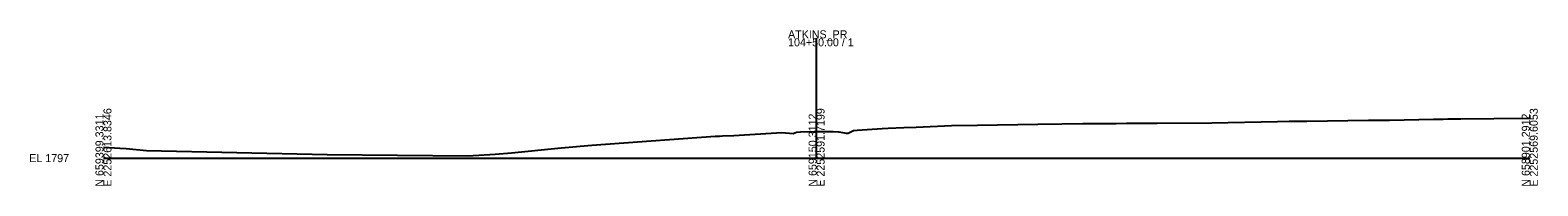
# Model space of a CAD drawing. Extents: x -11787 to 2342864, y -4773 to 646619.
# Drawn here: x 4530 to 5059, y 4059 to 4113 of the extents above; entities that cross this region are included whole.
import ezdxf

# ---------------------------------------------------------------- set-up
doc = ezdxf.new("R2010")
doc.units = 0
doc.layers.add('DESIGN - SHEET - Light Grid', color=7, linetype='Continuous')
doc.layers.add('SURVEY - GROUND - Top of Ground', color=7, linetype='Continuous')

msp = doc.modelspace()

# ---------------------------------------------------------------- linework, layer by layer
at = {"layer": 'DESIGN - SHEET - Light Grid'}
for p, q in [((4806.14, 4068.5), (4806.14, 4110.46)), ((4556.14, 4068.5), (4806.14, 4068.5)), ((4806.14, 4068.5), (5056.14, 4068.5))]:
    msp.add_line(p, q, dxfattribs=at)
at = {"layer": 'SURVEY - GROUND - Top of Ground'}
msp.add_lwpolyline([(4556.14, 4072.38), (4561.87, 4072.04), (4564.06, 4071.9), (4571.18, 4071.23), (4634.61, 4069.78), (4683.89, 4069.31), (4693.49, 4069.91), (4699.21, 4070.38), (4715.42, 4071.95), (4723.27, 4072.73), (4727.36, 4073.08), (4759.38, 4075.36), (4770.61, 4076.15), (4771.17, 4076.19), (4771.64, 4076.24), (4772.13, 4076.25), (4773.11, 4076.31), (4777.13, 4076.45), (4794, 4077.53), (4797.88, 4077.17), (4799.15, 4077.57), (4800.52, 4077.72), (4805.33, 4077.85), (4806.23, 4077.87), (4810.93, 4077.78), (4811.9, 4077.77), (4813.84, 4077.75), (4813.92, 4077.76), (4816.47, 4077.22), (4817.2, 4077.21), (4819.06, 4078.21), (4820.33, 4078.29), (4829.13, 4078.87), (4831.24, 4079.01), (4836.71, 4079.26), (4841.04, 4079.37), (4853.4, 4079.89), (4862.5, 4080.04), (4883.67, 4080.45), (4892.12, 4080.53), (4899.49, 4080.59), (4911.19, 4080.65), (4914.82, 4080.76), (4918.69, 4080.75), (4920.65, 4080.74), (4922.04, 4080.71), (4925.57, 4080.72), (4944.7, 4080.87), (4967.71, 4081.34), (4971.78, 4081.43), (4977.97, 4081.49), (4999.58, 4081.74), (5007.02, 4081.82), (5022.43, 4082.11), (5025.77, 4082.18), (5027.38, 4082.22), (5032.03, 4082.28), (5055.17, 4082.47), (5056.14, 4082.49)], dxfattribs=at)

# ---------------------------------------------------------------- texts
at = {"layer": 'DESIGN - SHEET - Light Grid'}
for s, p in [('ATKINS_PR', (4796.14, 4110.46)), ('104+50.00 / 1', (4796.14, 4107.66)), ('EL 1797', (4530.14, 4067.1))]:
    msp.add_text(s, height=2.8, dxfattribs=at).set_placement(p)
for s, p in [('E 2252613.8346', (4558.94, 4058.5)), ('E 2252591.7199', (4808.94, 4058.5)), ('E 2252569.6053', (5058.94, 4058.5)), ('N 659399.3311', (4556.14, 4058.5)), ('N 659150.3112', (4806.14, 4058.5)), ('N 658901.2912', (5056.14, 4058.5))]:
    msp.add_text(s, height=2.8, rotation=90, dxfattribs=at).set_placement(p)

doc.saveas('drawing.dxf')
